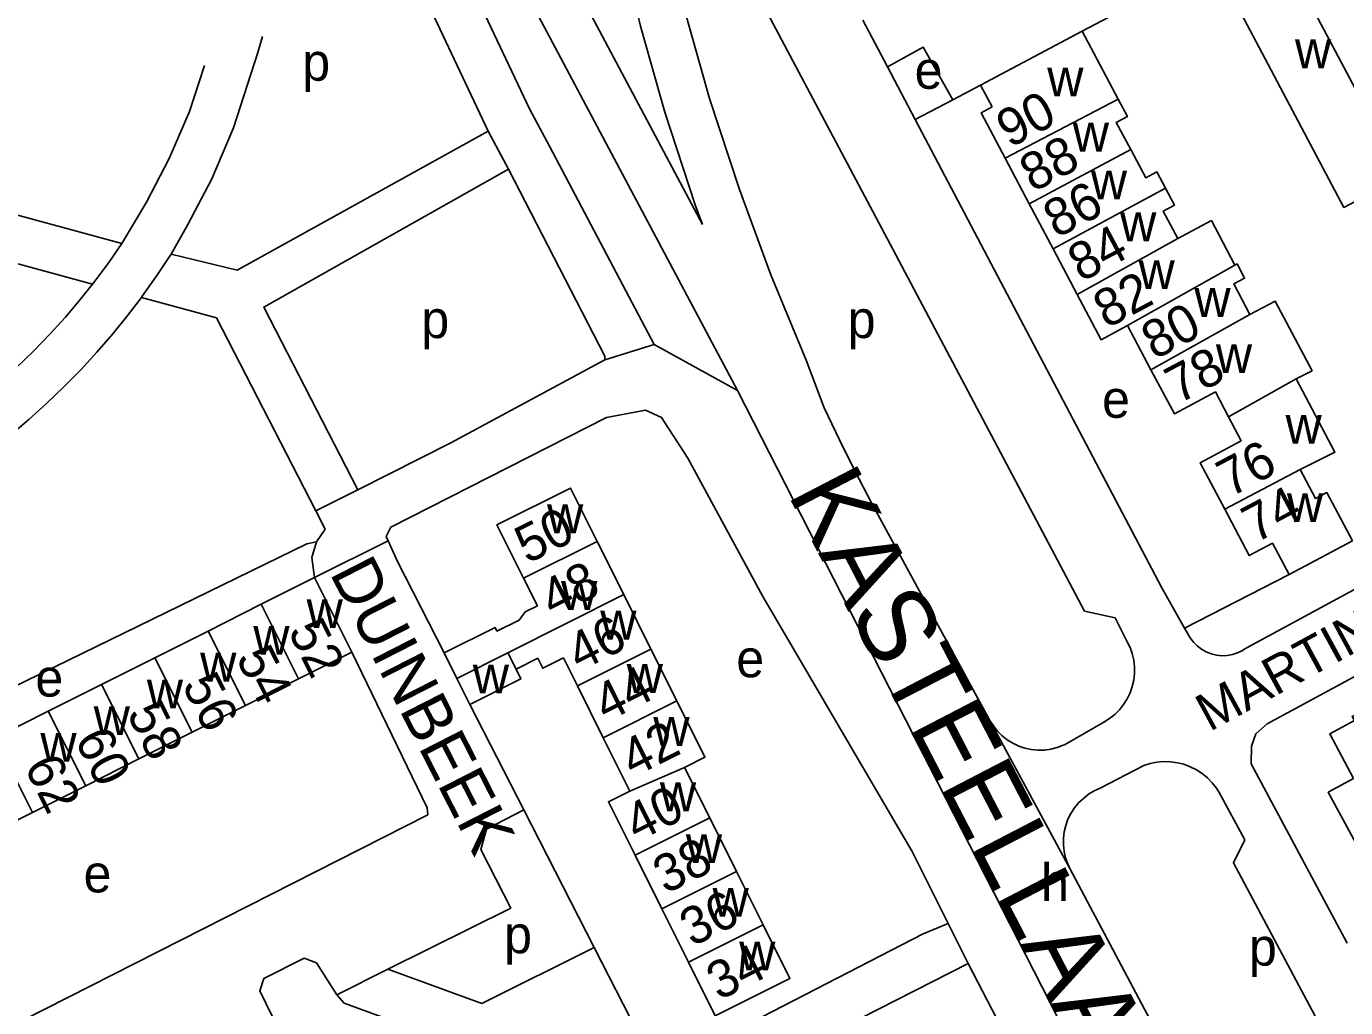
# Model space of a CAD drawing. Extents: x 157794 to 159375, y 380877 to 382306.
# Drawn here: x 158787.7 to 158928.4, y 381837.5 to 381942.2 of the extents above; entities that cross this region are included whole.
import ezdxf

# ---------------------------------------------------------------- set-up
doc = ezdxf.new("R2010")
doc.units = 0
for name, color, linetype in [('BLT_Basislijn', 7, 'Continuous'), ('BLT_Bebouwing', 7, 'Continuous'), ('BLT_Centroide', 7, 'Continuous'), ('BLT_Huisnummer', 7, 'Continuous'), ('BLT_Huisnummer_ tussenligend', 7, 'Continuous'), ('BLT_Onderverdeling_panden', 7, 'Continuous'), ('BLT_Straatnaam', 7, 'Continuous'), ('BLT_Straatnaam_hoofdweg', 7, 'Continuous'), ('BLT_Straatnaam_verkleind', 7, 'Continuous'), ('BLT_Vlakafsluiter', 7, 'Continuous')]:
    doc.layers.add(name, color=color, linetype=linetype)

msp = doc.modelspace()

# ---------------------------------------------------------------- linework, layer by layer
at = {"layer": 'BLT_Basislijn'}
for p, q in [((158832.99, 381951.1), (158841.35, 381933.37)), ((158912.09, 381947.86), (158900.32, 381941.66)), ((158880.45, 381917.79), (158865.81, 381945.35)), ((158876.92, 381942.82), (158879.54, 381937.85)), ((158879.54, 381937.85), (158882.51, 381932.22)), ((158889.49, 381935.91), (158886.51, 381934.33)), ((158841.35, 381933.37), (158843.53, 381929.33)), ((158886.51, 381934.33), (158882.51, 381932.22)), ((158882.51, 381932.22), (158908.82, 381882.28)), ((158836.95, 381930.99), (158839.13, 381926.95)), ((158843.53, 381929.33), (158854.65, 381908.25)), ((158778.84, 381924.16), (158797.88, 381919.01)), ((158854.65, 381908.25), (158863.55, 381903.34)), ((158823.03, 381892.76), (158818.56, 381890.51)), ((158877.86, 381891.36), (158890.48, 381868.16)), ((158819.56, 381888.57), (158818.56, 381890.51)), ((158819.56, 381888.57), (158818.64, 381887.19)), ((158818.42, 381883.39), (158826.28, 381887.3)), ((158911.26, 381878), (158922.4, 381883.73)), ((158908.82, 381882.28), (158911.26, 381878)), ((158911.26, 381878), (158911.57, 381877.47)), ((158898.45, 381865.57), (158902.65, 381867.97)), ((158902.24, 381860.92), (158906.9, 381863.36)), ((158840.77, 381858.63), (158848.26, 381843.95)), ((158899.02, 381852.38), (158907.58, 381836.23)), ((158886.04, 381846.51), (158888.17, 381842.24)), ((158836.27, 381837.98), (158848.26, 381843.95)), ((158826.26, 381841.62), (158820.8, 381838.9)), ((158826.26, 381841.62), (158836.27, 381837.98)), ((158901.18, 381817.18), (158888.17, 381842.24))]:
    msp.add_line(p, q, dxfattribs=at)
for points in [[(158859.8, 381921.03), (158859.03, 381923.12), (158855.8, 381933.02), (158853.19, 381942.18), (158852.88, 381943.53), (158849.78, 381959.69), (158849.64, 381960.89)], [(158870.88, 381906.58), (158867.12, 381915.67), (158863.75, 381924.76), (158860.58, 381934.48), (158858.03, 381943.44), (158857.77, 381944.57), (158854.72, 381960.45)], [(158835.19, 381958.78), (158835.87, 381956.9), (158837.31, 381953.15), (158839, 381949.51), (158863.55, 381903.34)], [(158840.44, 381958.99), (158840.56, 381958.65), (158841.92, 381955.1), (158843.48, 381951.74), (158859.8, 381921.03)], [(158828.51, 381948.87), (158836.95, 381930.99)], [(158812.86, 381941.09), (158812.36, 381939.37), (158809.79, 381931.35), (158807.45, 381925.91), (158804.91, 381921.04), (158803.11, 381917.87)], [(158879.54, 381937.85), (158883.35, 381939.96), (158886.51, 381934.33)], [(158806.68, 381938.01), (158805.1, 381933.1), (158802.93, 381928.06), (158800.51, 381923.43), (158797.88, 381919.01)], [(158803.11, 381917.87), (158810.17, 381916.16), (158836.95, 381930.99)], [(158839.13, 381926.95), (158813, 381912.23), (158823.03, 381892.76)], [(158839.13, 381926.95), (158849.4, 381907), (158849.4, 381906.6)], [(158794.74, 381914.68), (158775.37, 381919.94), (158760.43, 381897.03), (158739.76, 381887.35)], [(158794.74, 381914.68), (158794.99, 381915.01), (158796.48, 381917), (158797.88, 381919.01)], [(158799.95, 381913.27), (158800.05, 381913.41), (158801.54, 381915.5), (158802.96, 381917.63), (158803.11, 381917.87)], [(158905.17, 381876.48), (158903.85, 381879.09), (158900.59, 381879.81), (158880.45, 381917.79)], [(158778.99, 381899.51), (158780.99, 381901), (158782.93, 381902.55), (158784.82, 381904.16), (158786.66, 381905.82), (158788.44, 381907.55), (158790.17, 381909.33), (158791.84, 381911.17), (158793.45, 381913.06), (158794.74, 381914.68)], [(158781.92, 381895.46), (158783.97, 381896.99), (158785.98, 381898.58), (158787.94, 381900.24), (158789.84, 381901.95), (158791.69, 381903.73), (158793.48, 381905.56), (158795.21, 381907.44), (158796.89, 381909.38), (158798.5, 381911.37), (158799.95, 381913.27)], [(158818.56, 381890.51), (158807.96, 381911.1), (158799.95, 381913.27)], [(158849.4, 381906.6), (158832.98, 381897.77), (158823.03, 381892.76)], [(158877.86, 381891.36), (158876.1, 381894.71), (158874.42, 381898.09), (158872.81, 381901.5), (158870.88, 381906.58)], [(158968.91, 381903.93), (158967.57, 381902.79), (158917.68, 381875.79)], [(158863.55, 381903.34), (158916.5, 381799.68)], [(158826.28, 381887.3), (158826.07, 381887.78), (158826.56, 381888.78), (158849.57, 381900.46), (158853.72, 381901.24), (158855.45, 381900.46), (158858.24, 381896.11), (158866.27, 381881.37), (158882.2, 381854.19), (158886.04, 381846.51)], [(158928.61, 381844.41), (158918.34, 381863.52), (158918.4, 381865.43), (158918.84, 381866.73), (158920.07, 381867.79), (158968.02, 381893.72)], [(158764.9, 381863.02), (158769.38, 381865.78), (158770.43, 381865.78), (158771.07, 381864.72), (158772.62, 381865.07), (158817.6, 381887), (158818.64, 381887.19)], [(158818.64, 381887.19), (158818.15, 381885.54), (158818.42, 381883.39)], [(158832.24, 381875.36), (158827.26, 381885.11), (158826.28, 381887.3)], [(158911.57, 381877.47), (158911.84, 381876.97), (158912.19, 381876.51), (158912.59, 381876.1), (158913.05, 381875.75), (158913.55, 381875.46), (158914.09, 381875.25), (158914.65, 381875.12), (158915.22, 381875.06), (158915.79, 381875.09), (158916.36, 381875.19), (158916.91, 381875.37), (158917.42, 381875.63), (158917.68, 381875.79)], [(158822.4, 381875.45), (158830.44, 381858.83), (158830.5, 381858.1), (158746.44, 381815.46)], [(158902.65, 381867.97), (158903.25, 381868.35), (158903.81, 381868.79), (158904.31, 381869.3), (158904.75, 381869.85), (158905.13, 381870.45), (158905.44, 381871.09), (158905.67, 381871.77), (158905.83, 381872.46), (158905.9, 381873.17), (158905.9, 381873.88), (158905.82, 381874.58), (158905.66, 381875.28), (158905.43, 381875.95), (158905.17, 381876.48)], [(158840.77, 381858.63), (158834.99, 381869.86)], [(158890.48, 381868.16), (158890.85, 381867.57), (158891.28, 381867.02), (158891.78, 381866.53), (158892.33, 381866.1), (158892.92, 381865.73), (158893.55, 381865.43), (158894.21, 381865.21), (158894.9, 381865.06), (158895.59, 381864.99), (158896.29, 381865), (158896.98, 381865.09), (158897.66, 381865.26), (158898.31, 381865.51), (158898.45, 381865.57)], [(158906.9, 381863.36), (158907.59, 381863.58), (158908.3, 381863.71), (158909.03, 381863.77), (158909.76, 381863.75), (158910.48, 381863.65), (158911.18, 381863.48), (158911.86, 381863.22), (158912.51, 381862.89), (158913.12, 381862.5), (158913.68, 381862.04), (158914.19, 381861.52), (158914.64, 381860.94), (158914.93, 381860.48)], [(158902.24, 381860.92), (158901.6, 381860.64), (158901, 381860.28), (158900.45, 381859.85), (158899.94, 381859.37), (158899.5, 381858.83), (158899.12, 381858.24), (158898.81, 381857.62), (158898.57, 381856.96), (158898.41, 381856.28), (158898.33, 381855.59), (158898.33, 381854.89), (158898.4, 381854.19), (158898.56, 381853.51), (158898.79, 381852.85), (158899.02, 381852.38)], [(158914.93, 381860.48), (158917.68, 381855.43), (158916.46, 381852.99), (158933.59, 381820.86), (158936.19, 381819.94), (158937.89, 381816.8)], [(158840.77, 381858.63), (158836.76, 381856.55), (158836.15, 381854.4), (158839.36, 381848.15), (158826.26, 381841.62)], [(158886.04, 381846.51), (158883.37, 381845.39), (158854.74, 381830.66)], [(158854.74, 381830.66), (158852.91, 381834.83), (158848.26, 381843.95)], [(158820.8, 381838.9), (158818.63, 381842.3), (158817.32, 381842.82), (158813.02, 381840.65), (158812.58, 381839.33), (158816.65, 381831.01), (158821.15, 381833.32), (158827.8, 381820.04), (158823.35, 381817.8), (158824.66, 381815.17)], [(158850.12, 381826), (158851.06, 381824.05), (158851.63, 381823.65), (158888.17, 381842.24)], [(158820.8, 381838.9), (158821.58, 381838), (158831.39, 381834.43), (158829.7, 381830.29), (158831.54, 381826.6), (158833.39, 381825.99), (158834.77, 381823.38), (158827.86, 381816.62), (158824.66, 381815.17)]]:
    msp.add_lwpolyline(points, dxfattribs=at)
at = {"layer": 'BLT_Bebouwing'}
for p, q in [((158934.42, 381926.13), (158920.45, 381952.52)), ((158889.49, 381935.91), (158900.32, 381941.66)), ((158894.66, 381923.26), (158892.1, 381928.1)), ((158897.22, 381918.43), (158894.66, 381923.26)), ((158899.78, 381913.59), (158897.22, 381918.43)), ((158907.66, 381905.56), (158905.16, 381910.26)), ((158848.58, 381887.25), (158851.41, 381881.58)), ((158818.42, 381883.39), (158812.74, 381880.54)), ((158822.4, 381875.45), (158818.42, 381883.39)), ((158851.41, 381881.58), (158854.32, 381875.75)), ((158812.74, 381880.54), (158807.06, 381877.69)), ((158807.06, 381877.69), (158801.38, 381874.84)), ((158816.73, 381872.6), (158822.4, 381875.45)), ((158854.32, 381875.75), (158857.08, 381870.23)), ((158801.38, 381874.84), (158795.7, 381871.99)), ((158811.05, 381869.75), (158816.73, 381872.6)), ((158795.7, 381871.99), (158790.02, 381869.14)), ((158849.23, 381866.31), (158846.47, 381871.83)), ((158805.37, 381866.9), (158811.05, 381869.75)), ((158790.02, 381869.14), (158784.34, 381866.29)), ((158799.69, 381864.05), (158805.37, 381866.9)), ((158852.06, 381860.63), (158849.23, 381866.31)), ((158794.01, 381861.2), (158799.69, 381864.05)), ((158857.91, 381863.15), (158860.6, 381857.77)), ((158788.33, 381858.35), (158794.01, 381861.2)), ((158782.65, 381855.49), (158788.33, 381858.35)), ((158860.6, 381857.77), (158863.45, 381852.06)), ((158855.48, 381848.08), (158852.62, 381853.79)), ((158863.45, 381852.06), (158866.3, 381846.36)), ((158858.33, 381842.38), (158855.48, 381848.08))]:
    msp.add_line(p, q, dxfattribs=at)
for points in [[(158914.38, 381949.07), (158928.26, 381922.86), (158934.42, 381926.13)], [(158900.32, 381941.66), (158904.17, 381934.39)], [(158890.73, 381933.57), (158889.49, 381935.91)], [(158905.5, 381929.02), (158903.96, 381931.92), (158905.15, 381932.55), (158904.17, 381934.39)], [(158892.1, 381928.1), (158889.54, 381932.93), (158890.73, 381933.57)], [(158909.2, 381924.91), (158908.28, 381926.64), (158907.1, 381926.02), (158905.5, 381929.02)], [(158910.53, 381919.54), (158908.98, 381922.47), (158910.16, 381923.09), (158909.2, 381924.91)], [(158916.63, 381916.71), (158914.12, 381921.46), (158910.53, 381919.54)], [(158918.23, 381911.46), (158916.52, 381914.7), (158917.66, 381915.3), (158916.85, 381916.83), (158916.63, 381916.71)], [(158905.16, 381910.26), (158902.34, 381908.75), (158899.78, 381913.59)], [(158923.17, 381904.57), (158924.85, 381905.44), (158920.91, 381912.88), (158918.23, 381911.46)], [(158915.94, 381900.54), (158914.55, 381903.19), (158910.16, 381900.86), (158907.66, 381905.56)], [(158923.17, 381904.57), (158927.3, 381896.78), (158923.58, 381894.93)], [(158915.55, 381890.68), (158912.93, 381895.63), (158917.28, 381897.98), (158915.94, 381900.54)], [(158923.58, 381894.93), (158925.23, 381891.81), (158926.42, 381892.45), (158929.15, 381887.3)], [(158840.72, 381883.33), (158837.89, 381889.01), (158845.74, 381892.93), (158848.58, 381887.25)], [(158922.4, 381883.73), (158920.64, 381887.05), (158918.16, 381885.74), (158915.55, 381890.68)], [(158929.15, 381887.3), (158922.4, 381883.73)], [(158832.24, 381875.36), (158837.69, 381878.08), (158837.89, 381877.68), (158840.26, 381878.86), (158840.89, 381879.73), (158842.2, 381880.39), (158840.72, 381883.33)], [(158833.61, 381872.63), (158832.24, 381875.36)], [(158846.47, 381871.83), (158844.97, 381874.83), (158842.77, 381873.73), (158842.24, 381874.78), (158839.92, 381873.62)], [(158834.99, 381869.86), (158833.61, 381872.63)], [(158839.92, 381873.62), (158840.43, 381872.59), (158834.99, 381869.86)], [(158857.08, 381870.23), (158860.08, 381864.23), (158857.91, 381863.15)], [(158931.89, 381870.06), (158929.14, 381868.59), (158929.38, 381868.15), (158926.74, 381866.74), (158929.28, 381861.98), (158926.57, 381860.5), (158929.48, 381855.13), (158932.46, 381856.73), (158931.65, 381858.24), (158936.76, 381860.98)], [(158852.62, 381853.79), (158849.77, 381859.49), (158852.06, 381860.63)], [(158866.3, 381846.36), (158869.15, 381840.65), (158861.18, 381836.67), (158858.33, 381842.38)]]:
    msp.add_lwpolyline(points, dxfattribs=at)
at = {"layer": 'BLT_Onderverdeling_panden'}
for p, q in [((158892.1, 381928.1), (158904.17, 381934.39)), ((158894.66, 381923.26), (158905.5, 381929.02)), ((158897.22, 381918.43), (158909.2, 381924.91)), ((158899.78, 381913.59), (158910.53, 381919.54)), ((158905.16, 381910.26), (158916.63, 381916.71)), ((158907.66, 381905.56), (158918.23, 381911.46)), ((158923.17, 381904.57), (158915.94, 381900.54)), ((158915.55, 381890.68), (158923.58, 381894.93)), ((158840.72, 381883.33), (158848.58, 381887.25)), ((158839.05, 381875.35), (158851.41, 381881.58)), ((158816.73, 381872.6), (158812.74, 381880.54)), ((158811.05, 381869.75), (158807.06, 381877.69)), ((158833.61, 381872.63), (158839.05, 381875.35)), ((158839.05, 381875.35), (158839.92, 381873.62)), ((158846.47, 381871.83), (158854.32, 381875.75)), ((158805.37, 381866.9), (158801.38, 381874.84)), ((158799.69, 381864.05), (158795.7, 381871.99)), ((158849.23, 381866.31), (158857.08, 381870.23)), ((158794.01, 381861.2), (158790.02, 381869.14)), ((158788.33, 381858.35), (158784.34, 381866.29)), ((158852.06, 381860.63), (158857.91, 381863.15)), ((158852.62, 381853.79), (158860.6, 381857.77)), ((158855.48, 381848.08), (158863.45, 381852.06)), ((158858.33, 381842.38), (158866.3, 381846.36))]:
    msp.add_line(p, q, dxfattribs=at)
at = {"layer": 'BLT_Vlakafsluiter'}
for p, q in [((158854.65, 381908.25), (158849.4, 381906.6)), ((158890.48, 381868.16), (158899.02, 381852.38))]:
    msp.add_line(p, q, dxfattribs=at)

# ---------------------------------------------------------------- texts
at = {"layer": 'BLT_Centroide'}
for s, p in [('w', (158923.03, 381937.7)), ('p', (158817.11, 381936.37)), ('e', (158882.45, 381935.51)), ('w', (158896.6, 381934.69)), ('w', (158899.32, 381928.81)), ('w', (158901.25, 381923.72)), ('w', (158904.37, 381919.25)), ('w', (158906.34, 381914.16)), ('w', (158912.3, 381911.19)), ('p', (158829.82, 381908.93)), ('p', (158875.31, 381908.93)), ('w', (158914.59, 381905.19)), ('e', (158902.45, 381900.43)), ('w', (158922.02, 381897.66)), ('w', (158922.17, 381889.31)), ('w', (158843.23, 381888.12)), ('w', (158844.73, 381879.94)), ('w', (158817.58, 381878)), ('w', (158848.91, 381876.78)), ('w', (158811.89, 381875.16)), ('w', (158806.22, 381872.3)), ('e', (158863.42, 381872.76)), ('w', (158835.31, 381871.03)), ('w', (158851.73, 381871.09)), ('e', (158788.64, 381870.7)), ('w', (158800.53, 381869.44)), ('w', (158794.86, 381866.59)), ('w', (158854.57, 381865.44)), ('w', (158789.17, 381863.75)), ('w', (158855.27, 381858.47)), ('w', (158858.04, 381852.94)), ('e', (158793.78, 381849.82)), ('h', (158895.93, 381848.9)), ('w', (158860.89, 381847.22)), ('p', (158838.65, 381843.33)), ('w', (158863.73, 381841.5)), ('p', (158918.12, 381842.01))]:
    msp.add_text(s, height=4, dxfattribs=at).set_placement(p)
at = {"layer": 'BLT_Huisnummer'}
for s, rotation, p in [('90', 27.9271, (158892.59, 381929.14)), ('86', 27.9271, (158897.59, 381919.52)), ('82', 27.9271, (158902.93, 381909.89)), ('78', 27.9271, (158910.59, 381901.85)), ('74', 27.9271, (158918.79, 381887.01)), ('50', 26.5449, (158841.12, 381884.81)), ('52', 296.6574, (158815.54, 381877.7)), ('46', 26.5449, (158846.68, 381873.34)), ('56', 296.6574, (158804.23, 381871.95)), ('60', 296.6574, (158792.77, 381866.12)), ('42', 26.5449, (158852.4, 381862.04)), ('38', 26.5449, (158855.87, 381849.6)), ('34', 26.5449, (158861.57, 381838.25))]:
    msp.add_text(s, height=4, rotation=rotation, dxfattribs=at).set_placement(p)
at = {"layer": 'BLT_Huisnummer_ tussenligend'}
for s, rotation, p in [('88', 27.9271, (158895.07, 381924.42)), ('84', 27.9271, (158900.21, 381914.85)), ('80', 27.9271, (158908.05, 381906.56)), ('76', 27.9271, (158916.1, 381891.9)), ('48', 26.5449, (158843.83, 381879.08)), ('54', 296.6574, (158809.98, 381874.84)), ('44', 26.5449, (158849.53, 381867.93)), ('58', 296.6574, (158798.34, 381868.91)), ('62', 296.6574, (158787.39, 381863.25)), ('40', 26.5449, (158852.83, 381855.16)), ('36', 26.5449, (158858.71, 381843.98))]:
    msp.add_text(s, height=4, rotation=rotation, dxfattribs=at).set_placement(p)
at = {"layer": 'BLT_Straatnaam'}
msp.add_text('DUINBEEK', height=5, rotation=297.0327, dxfattribs=at).set_placement((158819.99, 381883.89))
at = {"layer": 'BLT_Straatnaam_hoofdweg'}
msp.add_text('KASTEELLAAN', height=8, rotation=297.4183, dxfattribs=at).set_placement((158868.83, 381892.36))
at = {"layer": 'BLT_Straatnaam_verkleind'}
msp.add_text('MARTIN LUTHER KINGSTRAAT', height=4, rotation=28.5304, dxfattribs=at).set_placement((158913.91, 381866.91))

doc.saveas('drawing.dxf')
